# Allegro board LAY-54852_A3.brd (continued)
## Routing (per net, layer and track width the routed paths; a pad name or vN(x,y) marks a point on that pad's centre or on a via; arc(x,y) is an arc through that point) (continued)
POR_B: length 193.2
  TOP w0.091: R1743.2 v1(21.25,61.23) ; v1(48.82,73.05) 51.12,73.05 51.5,73.43 57.77,73.43 61.17,70.03 70.32,70.03 70.42,69.93 91.77,69.93 94.34,67.36 95.41,67.36 97.79,64.98 97.79,64.55 98.31,64.04 R404.1 98.85,64.04 98.94,64.13 98.94,64.96 99.12,65.13 100.02,65.13 100.32,64.82 U802.2 ; v1(33.38,72.69) 33.74,73.05 v1(42.33,73.05) ; v1(32.35,64.88) 32.35,64.88 31.95,65.28 26.19,65.28 25.04,66.43 24.07,66.43 21.5,68.99 v1(21.5,69.19) ; Q1408.1 v1(21.38,65.39) ; D1408.A 23.22,45.01 v1(21.72,45.01) 20.57,46.16 19.79,46.16 19.22,46.73 19.22,48.14 19.31,48.24 24.11,48.24 24.21,48.14 24.21,46.91 24.51,46.6 32.37,46.6 33.33,47.56 42.86,47.56 43.97,48.66 46.9,48.66 49.3,51.06 v1(49.53,51.06)
  TOP w0.104: U701.9 60.89,29.95 60.36,29.43 55.39,29.43 54.75,28.8 v1(54.5,28.8)
  BOTTOM w0.091: v1(21.72,45.01) 22.85,46.13 22.85,59.38 21.25,60.98 v1(21.25,61.23) 21.62,61.61 21.62,65.15 v1(21.38,65.39) 21.38,69.07 v1(21.5,69.19) ; v1(32.35,64.88) 32.44,64.88 32.82,65.26 32.82,72.13 v1(33.38,72.69) ; v1(42.33,73.05) v1(48.82,73.05) ; v1(54.5,28.8) 50.98,32.31 50.98,46.11 49.53,47.56 v1(49.53,51.06)
RC_BT_MODE0: length 24.8
  TOP w0.091: U1404.15 29.5,64.31 29.87,64.68 31.58,64.68 40.82,55.44 40.82,52.24 39.64,51.05 SW601.7 37.25,51.05 R608.1 R609.1
RC_BT_MODE1: length 22.8
  TOP w0.091: U1404.14 29.9,64.37 29.99,64.46 31.49,64.46 40.51,55.44 40.51,53.01 39.83,52.32 SW601.5 37.8,52.32 37.25,52.88 R607.1 R610.1
RC_BT_MODE2: length 20.3
  TOP w0.091: U1404.13 31.8,63.84 37.29,58.35 37.29,57.23 38.82,55.7 39.79,55.7 40.2,55.28 40.2,53.89 39.91,53.59 SW601.3 37.21,53.59 R606.1 R611.1
RC_BT_MODE3: length 13.1
  TOP w0.091: U1404.12 32.1,63.23 36.75,58.58 R605.1 R612.1 38.08,54.86 SW601.1
RC_NSEL: length 65.3
  TOP w0.091: R1815.2 8.79,69.97 8.38,70.39 7.82,70.39 6.95,69.52 5.41,69.52 5.12,69.23 5.12,67.48 5.03,67.39 3.42,67.39 D1413.C ; R1815.2 8.79,68.75 Q1405.3 ; R1815.2 10.54,69.88 11.61,70.95 16.21,70.95 16.61,70.55 16.61,69.24 17.13,68.72 21.47,68.72 23.98,66.21 24.73,66.21 v1(25.56,65.38) 25.87,65.06 28.34,65.06 29.1,64.3 U1404.16 29.07,63.81 U1404.1 ; v1(20.54,39.32) 20.84,39.02 U1408.12
  BOTTOM w0.091: v1(25.56,65.38) 24.93,64.75 24.93,61.21 23.28,59.57 23.28,45.13 20.54,42.38 v1(20.54,39.32)
RC_SEL: length 48.1
  TOP w0.091: D1412.C 3.17,65.15 4.81,65.15 5.67,66.01 6.37,66.01 6.55,66.19 R1754.1 ; v1(12.71,65.65) 9.15,65.65 8.16,66.63 Q1405.1 7.41,66.83 7.17,66.59 R1754.1 ; R1752.2 6.55,66.59 R1754.1 ; R1449.2 28.15,51.41 26.24,53.33 25.06,53.33 24.8,53.07 24.8,50.8 22.8,48.8 17.64,48.8 14.8,51.65 v1(14.42,51.65)
  BOTTOM w0.091: v1(12.71,65.65) 12.59,65.65 12.09,65.15 12.09,60.55 13.98,58.66 13.98,52.09 v1(14.42,51.65)
REG_FT_1V8: length 5.9
  TOP w0.254: U1706.49 3.72,31.37 C1422.1
  TOP w0.508: L1404.2 2.07,34.74 3.45,33.36 C1421.1 3.55,32.8 C1422.1
RTC_CLKO: length 124.2
  TOP w0.091: v1(48.43,48.34) 47.12,47.03 v1(44.25,47.03) ; R959.2 119.84,25.16 119.93,25.26 121.08,25.26 122.53,23.8 v1(122.53,16.41)
  BOTTOM w0.091: U1004.6 44.15,50.04 44.5,49.69 44.5,48.57 44.83,48.24 TP1021.1 v1(44.25,47.03) ; v1(48.43,48.34) 50.51,46.26 50.51,37.29 49.71,36.49 49.71,30.73 53.66,26.78 53.66,19.33 55.2,17.78 66.53,17.78 66.99,17.32 78.4,17.32 79.21,16.52 96.72,16.52 98.97,18.77 113.12,18.77 114.2,17.7 114.96,17.7 116.21,16.44 122.5,16.44 v1(122.53,16.41)
RTC_NINTA: length 120.2
  TOP w0.091: R807.2 107.11,56.43 106.88,56.2 v1(106.65,56.2)
  BOTTOM w0.091: v1(106.65,56.2) 106.65,56.97 107.56,57.88 107.56,66.29 106.29,67.57 106.29,71.43 105.4,72.32 104.16,72.32 101.76,74.72 90.64,74.72 87.22,71.3 84.98,71.3 84.55,71.72 82.21,71.72 82.21,71.73 81.42,71.73 81.06,71.36 73.73,71.36 68.44,76.66 54.91,76.66 48.65,70.4 48.65,66.61 48.07,66.02 43.51,66.02 32.53,55.04 32.53,52.64 33.02,52.15 34.44,52.15 35.84,50.75 TP1019.1
  BOTTOM w0.203: R1075.2 37.43,49.71 R1084.1 38.21,50.66 TP1019.1 38.59,51.04 U1004.13
SAI1_RXD0: length 82.6
  TOP w0.081: 91.24,57 91.24,56.45 U101.B14
  TOP w0.091: 91.24,57 91.24,58.39 93.28,60.43 95.11,60.43 96.85,58.69 98.5,58.69 102.78,54.41 114.31,54.41 116.64,56.74 116.64,58.59 119.03,60.97 123.64,60.97 123.8,60.82 126.42,60.82 127.14,61.54 128.2,61.54 v1(128.37,61.37) ; R909.1 126.36,28.84 125.79,29.41 125.79,32.29 125.23,32.84 v1(125.23,33.5)
  BOTTOM w0.091: v1(128.37,61.37) 128.22,61.23 128.22,38.42 125.23,35.44 v1(125.23,33.5)
SAI1_TXC: length 82.4
  TOP w0.081: U101.B15 91.49,56.35 91.75,56.61 91.75,56.86
  TOP w0.091: R1784.1 129.64,28.18 128.84,28.99 128.23,28.99 127.09,30.12 127.09,33.24 126.1,34.23 124.42,34.23 v1(124.33,34.14) ; 91.75,56.86 91.75,58.28 92.22,58.75 93.05,58.75 93.85,57.95 98.62,57.95 102.59,53.97 114.49,53.97 117.08,56.56 117.08,58.29 119.17,60.38 126.6,60.38 126.96,60.74 127.46,60.74 v1(127.62,60.58)
  BOTTOM w0.091: v1(124.33,34.14) 124.33,35.14 127.78,38.59 127.78,60.35 127.62,60.51 v1(127.62,60.58)
SAI1_TXD0: length 222.2
  TOP w0.091: v1(125.75,33.3) 126.28,32.77 126.28,29.84 127.44,28.68 R1786.1 ; U101.A15 91.49,58.33 93.37,60.21 95.02,60.21 96.92,58.31 98.57,58.31 102.68,54.19 114.4,54.19 116.86,56.65 116.86,58.5 119.12,60.75 123.55,60.75 123.71,60.6 126.51,60.6 127.14,61.24 127.74,61.24 127.98,61 128.62,61 v1(128.93,61.31)
  TOP w0.381: R605.2 35.91,57.18 TP604.1 34.65,57.71 34.18,58.18 v1(34.18,58.77)
  BOTTOM w0.091: v1(125.75,33.3) 125.75,35.64 128.44,38.33 128.44,60.82 v1(128.93,61.31) 129.43,61.81 129.43,79.63 125.53,83.54 40.32,83.54 36.62,79.84 36.62,61.28 34.18,58.84 v1(34.18,58.77)
SAI1_TXFS: length 228.3
  TOP w0.091: v1(128.3,61.9) 128.11,61.9 127.09,62.92 125.01,62.92 123.49,61.4 119.14,61.4 116.42,58.68 116.42,56.83 114.22,54.63 102.87,54.63 98.59,58.91 96.94,58.91 95.2,60.65 93.19,60.65 90.99,58.45 U101.A14 ; v1(33.71,57.95) 33.71,56.99 34.65,56.05 TP603.1 34.87,54.06 R606.2 ; R1785.1 128.54,28.36 126.65,30.25 126.65,33.17 125.88,33.95 125.13,33.95 v1(124.7,33.52)
  BOTTOM w0.091: v1(33.71,57.95) 33.95,57.95 36.84,60.84 36.84,79.75 40.41,83.32 125.44,83.32 129.2,79.55 129.2,62.8 v1(128.3,61.9) 127.99,61.59 127.99,38.5 124.7,35.21 v1(124.7,33.52)
SAI3_MCLK: length 56.1
  TOP w0.091: U804.3 100.69,72.95 101.25,73.5 v1(101.4,73.5) ; v1(102.35,33.9) 102.35,32.23 R1209.1
  BOTTOM w0.091: v1(102.35,33.9) 102.88,34.44 109.6,34.44 112.02,36.86 112.02,46.68 100.99,57.71 100.99,72.27 101.4,72.68 v1(101.4,73.5)
SAI3_RXC: length 63.3
  TOP w0.091: v1(109.51,29.27) 109.23,29.55 108.16,29.55 R1206.1 ; U803.3 v1(132.71,71.5)
  BOTTOM w0.091: v1(109.51,29.27) 109.51,30.17 111.2,31.85 126.05,31.85 126.65,32.45 126.65,35.61 129.1,38.06 129.1,56.17 132.68,59.75 132.68,69.17 132.03,69.82 132.03,70.82 v1(132.71,71.5)
SAI3_RXD: length 62.1
  TOP w0.091: U803.12 v1(129.81,70.7) ; R1208.1 v1(108.76,29.18)
  BOTTOM w0.091: v1(129.81,70.7) 131.81,68.7 131.81,61.72 128.66,58.57 128.66,38.24 126.21,35.79 126.21,32.63 125.87,32.29 111.02,32.29 108.76,30.03 v1(108.76,29.18)
SAI3_RXFS: length 63.3
  TOP w0.091: v1(109.46,28.53) 109.35,28.42 109.35,27.79 R1205.1 ; U803.16 v1(132.57,70.09)
  BOTTOM w0.091: v1(132.57,70.09) 132.91,69.75 132.91,59.61 129.32,56.02 129.32,37.97 126.86,35.52 126.86,32.35 126.14,31.63 111.29,31.63 109.89,30.23 109.89,29.06 109.46,28.63 v1(109.46,28.53)
SAI3_TXD: length 65.2
  TOP w0.091: v1(108.76,28.54) 108.76,28.19 R1207.1 ; U803.9 130.21,71.9 v1(129.81,72.3)
  BOTTOM w0.091: v1(108.76,28.54) 109.14,28.92 109.14,30.1 111.11,32.07 125.96,32.07 126.43,32.54 126.43,35.7 128.88,38.15 128.88,56.46 131.74,59.32 131.74,60.26 132.25,60.77 132.25,68.88 130.76,70.36 130.76,71.24 129.81,72.19 v1(129.81,72.3)
SD1_CLK: length 23.8
  TOP w0.081: U501.M6 105.23,38.65 105.23,37.45
  TOP w0.091: U101.U11 89.49,46.51 97.81,38.19 98.88,38.19 TP503.1 101.15,38.14 102.43,36.87 104.82,36.87 105.23,37.28 105.23,37.45
SD1_CMD: length 23.9
  TOP w0.081: 101.87,39.15 104.23,39.15 U501.M5 ; 89.74,48.76 89.74,48.24
  TOP w0.091: 89.74,48.76 89.74,48.96 U101.T11 ; 89.74,48.24 89.74,46.57 95.58,40.74 TP502.1 97.22,40.23 97.31,40.14 98.14,40.14 98.26,40.02 R502.2 98.26,39.36 99.08,38.55 99.23,38.55 99.37,38.69 99.37,39.14 99.43,39.2 99.67,39.2 99.73,39.14 99.73,38.7 99.88,38.55 99.88,38.55 100.13,38.55 100.32,38.74 100.32,39.02 100.41,39.11 100.72,39.11 100.82,39.02 100.82,38.72 100.99,38.55 101.56,38.55 101.65,38.64 101.65,38.93 101.87,39.15
SD1_DATA0: length 23.9
  TOP w0.076: U101.T13 90.74,48.95
  TOP w0.081: 90.74,47.26 91.26,46.74 ; 90.74,48.95 90.74,48.21 ; 102.33,44.65 103.24,44.65
  TOP w0.091: 103.24,44.65 U501.A3 ; 102.33,44.65 101.85,44.16 101.38,44.16 101.1,43.89 101.1,43.28 101.01,43.19 100.72,43.19 100.59,43.32 100.08,43.32 99.99,43.23 99.99,43 100.1,42.89 100.23,42.89 100.32,42.8 100.32,42.67 100.23,42.58 99.73,42.58 99.61,42.69 99.61,43.23 99.44,43.41 98,43.41 97.81,43.22 R501.2 97.4,42.84 97.16,43.07 97.16,43.85 97.09,43.92 96.84,43.92 96.75,43.83 TP501.1 96.37,42.87 96.28,42.96 96.28,43.85 96.18,43.94 96,43.94 95.91,43.85 95.91,42.96 95.82,42.87 94.94,42.87 91.26,46.55 91.26,46.74 ; 90.74,48.21 90.74,47.26
SD1_DATA1: length 23.7
  TOP w0.081: 91.25,47.79 91.58,47.46 91.58,47.35 91.47,47.25 91.47,47.13 91.59,47.02 91.7,47.02 91.76,47.07 91.88,47.07 ; U101.T14 91.25,48.95 91.25,48.2
  TOP w0.091: U501.A4 104.06,44.48 104.06,45.14 103.97,45.23 101.06,45.23 100.97,45.14 100.97,44.48 100.88,44.39 97.42,44.39 97.3,44.51 97.3,44.99 97.19,45.09 97.06,45.09 96.96,44.99 96.96,44.51 96.87,44.41 96.69,44.41 96.6,44.51 96.6,45.09 96.51,45.18 96.33,45.18 96.24,45.09 96.24,44.51 96.14,44.41 95.96,44.41 95.87,44.51 95.87,45.09 95.78,45.18 95.6,45.18 95.5,45.09 95.5,44.51 95.41,44.41 95.23,44.41 95.14,44.51 95.14,44.9 95.05,44.99 94.86,44.99 94.77,44.9 94.77,44.51 94.68,44.41 94.25,44.41 94.17,44.5 94.17,44.67 94.2,44.71 94.36,44.71 94.41,44.76 94.41,44.91 94.32,45 93.65,45 93.47,45.17 93.47,45.41 93.32,45.56 93.08,45.56 92.96,45.69 92.96,45.82 93.01,45.87 93.01,46.05 92.92,46.15 92.77,46.15 92.7,46.08 92.57,46.08 92.44,46.21 92.44,46.34 92.45,46.35 92.45,46.5 91.88,47.07 ; 91.25,48.2 91.25,47.79
SD1_DATA2: length 23.8
  TOP w0.081: 91.74,47.99 92.11,47.62 92.79,47.62 92.87,47.54 92.87,47.17 92.95,47.08 93.11,47.08 93.19,47.17 93.19,47.54 93.27,47.62 93.44,47.62 93.52,47.54 93.52,47.17 93.6,47.08 93.76,47.08 93.84,47.17 93.84,47.54 93.92,47.62 94.78,47.62 ; U101.T15 91.49,49.06 91.74,48.81 91.74,48.4
  TOP w0.091: 91.74,47.99 91.74,48.4 ; U501.A5 104.75,44.67 104.75,45.05 104.92,45.22 105.16,45.22 105.34,45.4 105.34,45.53 105.06,45.81 104.49,45.81 104.38,45.7 100.19,45.7 100.1,45.79 100.1,46.13 100.01,46.22 99.82,46.22 99.73,46.13 99.73,45.79 99.64,45.7 99.46,45.7 99.37,45.79 99.37,46.13 99.27,46.22 99.09,46.22 99,46.13 99,45.79 98.91,45.7 98.73,45.7 98.63,45.79 98.63,46.13 98.54,46.22 98.36,46.22 98.27,46.13 98.27,45.79 98.18,45.7 97.99,45.7 97.9,45.79 97.9,46.13 97.81,46.22 97.63,46.22 97.54,46.13 97.54,45.79 97.45,45.7 97.26,45.7 97.17,45.79 97.17,46.13 97.08,46.22 96.9,46.22 96.81,46.13 96.81,45.79 96.71,45.7 96.53,45.7 96.44,45.79 96.44,46.18 95,47.62 94.78,47.62
SD1_DATA3: length 23.8
  TOP w0.076: 102.28,44.05 102.39,44.15 102.73,44.15 U501.B2
  TOP w0.091: U101.U13 90.49,46.9 95.17,42.22 96.18,42.22 96.27,42.13 96.27,41.88 96.36,41.79 96.54,41.79 96.64,41.88 96.64,42.13 96.73,42.22 96.91,42.22 97,42.13 97,41.88 97.09,41.79 97.28,41.79 97.37,41.88 97.37,42.13 97.46,42.22 97.64,42.22 97.73,42.13 97.73,41.88 97.82,41.79 98.01,41.79 98.1,41.88 98.1,42.13 98.19,42.22 98.37,42.22 98.46,42.13 98.46,41.88 98.56,41.79 98.74,41.79 98.83,41.88 98.83,42.13 98.92,42.22 99.1,42.22 99.2,42.13 99.2,41.88 99.29,41.79 99.47,41.79 99.56,41.88 99.56,42.13 99.65,42.22 99.84,42.22 99.93,42.13 99.93,41.88 100.02,41.79 100.2,41.79 100.29,41.88 100.29,42.13 100.39,42.22 100.57,42.22 100.66,42.13 100.66,41.88 100.75,41.79 100.93,41.79 101.15,42.01 101.45,42.01 101.57,41.89 101.57,41.85 101.63,41.79 101.82,41.79 101.89,41.86 101.89,42.22 101.81,42.31 101.49,42.31 101.41,42.38 101.41,43.85 101.51,43.95 102.18,43.95 102.28,44.05
SD1_DATA4: length 23.8
  TOP w0.076: 102.34,43.65 103.23,43.65 U501.B3
  TOP w0.081: 90.24,48.22 90.24,48.95 U101.T12
  TOP w0.091: 102.34,43.65 101.82,43.65 101.72,43.55 101.72,42.66 101.78,42.61 102.01,42.61 102.15,42.46 102.15,41.21 102.07,41.12 101.84,41.12 101.75,41.22 101.75,41.48 101.66,41.57 101.13,41.57 101.03,41.48 101.03,41.27 100.94,41.18 100.76,41.18 100.67,41.27 100.67,41.48 100.58,41.57 100.39,41.57 100.3,41.48 100.3,41.27 100.21,41.18 100.03,41.18 99.94,41.27 99.94,41.48 99.85,41.57 99.66,41.57 99.57,41.48 99.57,41.27 99.48,41.18 99.3,41.18 99.21,41.27 99.21,41.48 99.11,41.57 98.93,41.57 98.84,41.48 98.84,41.27 98.75,41.18 98.57,41.18 98.47,41.27 98.47,41.4 98.38,41.49 95.52,41.49 90.24,46.76 90.24,48.22
SD1_DATA5: length 23.7
  TOP w0.076: U501.B4 103.73,44.15 103.73,44.87
  TOP w0.081: 90.99,47.67 91.14,47.52
  TOP w0.091: 91.14,47.52 91.14,47.19 94.18,44.16 94.98,44.16 95.07,44.06 95.07,43.31 95.2,43.18 95.45,43.18 95.54,43.28 95.54,43.99 95.71,44.16 97.22,44.16 97.42,43.95 97.42,43.55 97.5,43.46 97.7,43.46 97.77,43.54 97.77,44.06 97.86,44.16 98.05,44.16 98.14,44.06 98.14,43.72 98.24,43.63 98.42,43.63 98.51,43.72 98.51,44.06 98.6,44.16 98.8,44.16 98.89,44.06 98.89,43.78 98.98,43.68 99.17,43.68 99.26,43.78 99.26,44.06 99.35,44.16 99.53,44.16 99.62,44.06 99.62,43.78 99.71,43.68 99.9,43.68 99.99,43.78 99.99,44.06 100.08,44.16 100.26,44.16 100.35,44.06 100.35,43.78 100.45,43.68 100.63,43.68 100.72,43.78 100.72,44.06 100.81,44.16 101,44.16 101.27,44.42 101.27,44.87 101.36,44.97 101.58,44.97 101.7,44.85 101.7,44.57 101.79,44.48 101.92,44.48 102.01,44.57 102.01,44.85 102.13,44.97 103.64,44.97 103.73,44.87 ; U101.U14 90.99,47.67
SD1_DATA6: length 24
  TOP w0.076: U501.B5 104.33,43.9 104.23,44 104.23,44.66
  TOP w0.081: 92.44,47.05 92.35,47.14 92.28,47.14 91.49,47.93
  TOP w0.091: 104.23,44.66 104.54,44.96 104.54,45.39 104.45,45.48 100.26,45.48 100.17,45.39 100.17,45.14 100.3,45.01 100.61,45.01 100.68,44.93 100.68,44.7 100.59,44.61 99.9,44.61 99.81,44.7 99.81,45.39 99.72,45.48 99.53,45.48 99.44,45.39 99.44,44.7 99.35,44.61 99.17,44.61 99.07,44.7 99.07,45.39 98.98,45.48 98.8,45.48 98.71,45.39 98.71,44.7 98.62,44.61 98.43,44.61 98.34,44.7 98.34,45.39 98.25,45.48 98.07,45.48 97.98,45.39 97.98,44.7 97.89,44.61 97.7,44.61 97.61,44.7 97.61,45.37 97.52,45.47 95.35,45.47 95.11,45.22 94.09,45.22 93.32,46 93.32,46.17 92.44,47.05 ; 91.49,47.93 U101.U15
SD1_DATA7: length 23.9
  TOP w0.076: U501.B6 105.23,44.15 105.63,44.15 105.74,44.25 105.74,44.49
  TOP w0.081: 94.6,47.87 94.55,47.92 92.21,47.92 91.99,48.13
  TOP w0.091: 105.74,44.49 105.74,44.84 106.02,45.12 106.37,45.12 106.56,45.32 106.56,46.35 106.47,46.44 105.37,46.44 105.27,46.35 105.27,46.24 105.18,46.15 105,46.15 104.91,46.24 104.91,46.28 104.75,46.43 104.13,46.43 104.04,46.34 104.04,46.01 103.95,45.92 103.53,45.92 103.44,46.01 103.44,46.35 103.34,46.44 103.16,46.44 103.07,46.35 103.07,46.01 102.98,45.92 102.8,45.92 102.7,46.01 102.7,46.35 102.61,46.44 102.42,46.44 102.33,46.35 102.33,46.01 102.24,45.92 102.05,45.92 101.96,46.01 101.96,46.35 101.87,46.44 101.69,46.44 101.6,46.35 101.6,46.01 101.51,45.92 101.32,45.92 101.23,46.01 101.23,46.35 101.14,46.44 100.96,46.44 100.87,46.35 100.87,46.01 100.77,45.92 100.59,45.92 100.5,46.01 100.5,46.35 100.41,46.44 96.51,46.44 95.09,47.87 94.6,47.87 ; 91.99,48.13 U101.U16
SD1_STROBE: length 23.7
  TOP w0.081: 101.87,40.65 104.24,40.65 U501.H5
  TOP w0.091: 101.87,40.65 101.41,40.65 101.32,40.56 101.32,40.11 101.22,40.02 101.04,40.02 100.95,40.11 100.95,40.56 100.86,40.65 100.68,40.65 100.58,40.56 100.58,40.11 100.49,40.02 100.31,40.02 100.22,40.11 100.22,40.56 100.13,40.65 99.85,40.65 99.75,40.56 99.75,40.03 99.6,39.88 99.47,39.88 99.28,40.07 99.28,40.54 TP505.1 98.81,40.75 98.72,40.66 98.72,40.23 98.63,40.14 98.44,40.14 98.35,40.23 98.35,40.97 98.06,41.26 95.37,41.26 89.99,46.63 U101.U12
SD2_CLK: length 35.4
  TOP w0.081: 92.69,50.95 92.25,50.95 U101.M16
  TOP w0.091: 92.69,50.95 95.54,50.95 96.63,49.87 118.53,49.87 118.63,49.97 118.63,50.08 118.53,50.17 118.11,50.17 118.02,50.26 118.02,50.4 118.11,50.5 118.54,50.5 118.63,50.59 118.63,51.69 118.77,51.83 119.54,51.83 119.63,51.92 119.63,52.05 119.53,52.14 118.72,52.14 118.63,52.23 118.63,52.9 118.72,52.99 119.43,52.99 119.8,52.63 120.6,52.63 R1061.1
SD2_CMD: length 35.4
  TOP w0.091: U101.M17 95.6,51.21 96.72,50.08 117.35,50.08 118.41,51.14 118.41,53.57 118.58,53.74 118.99,53.74 119.08,53.83 119.08,54.03 118.99,54.13 118.61,54.13 118.41,54.33 118.41,54.88 119.09,55.56 R311.2 120.84,55.58 R1060.1
SD2_DATA0: length 36.4
  TOP w0.091: U101.N17 95.48,50.71 96.53,49.65 98.42,49.65 98.51,49.56 98.51,49.15 98.6,49.06 98.78,49.06 98.87,49.15 98.87,49.56 98.96,49.65 99.15,49.65 99.24,49.56 99.24,49.15 99.33,49.06 99.51,49.06 99.6,49.15 99.6,49.56 99.7,49.65 99.88,49.65 99.97,49.56 99.97,49.15 100.06,49.06 100.24,49.06 100.34,49.15 100.34,49.56 100.43,49.65 117,49.65 117.21,49.44 117.21,48.91 117.35,48.77 117.57,48.77 117.67,48.86 117.67,49.51 117.8,49.65 117.99,49.65 118.09,49.56 118.09,49.04 118.18,48.95 118.43,48.95 118.49,49.01 118.49,49.52 118.62,49.65 118.91,49.65 119.1,49.83 119.1,50.63 119.51,51.04 119.96,51.04 120.17,50.83 R1062.1 120.84,50.84 R310.2
SD2_DATA1: length 35.5
  TOP w0.081: 92.78,50.46 92.24,50.46 U101.N16
  TOP w0.091: R1063.1 120.37,50.24 119.69,50.24 119.43,49.99 119.43,48.69 119.06,48.31 118.6,48.31 118.51,48.4 118.51,48.52 118.42,48.62 118.24,48.62 118.14,48.52 118.14,48.4 118.05,48.31 117.44,48.31 116.99,48.76 116.99,49.26 116.82,49.43 107.12,49.43 106.53,48.84 105.33,48.84 105.24,48.94 105.24,48.98 105.15,49.07 104.96,49.07 104.87,48.98 104.87,48.94 104.78,48.84 104.6,48.84 104.51,48.94 104.51,49.17 104.42,49.26 104.23,49.26 104.14,49.17 104.14,48.94 104.05,48.84 103.87,48.84 103.78,48.94 103.78,49.17 103.68,49.26 103.5,49.26 103.41,49.17 103.41,48.94 103.32,48.84 103.14,48.84 103.04,48.94 103.04,49.17 102.95,49.26 102.77,49.26 102.68,49.17 102.68,48.94 102.59,48.84 102.4,48.84 102.31,48.94 102.31,49.17 102.22,49.26 102.04,49.26 101.95,49.17 101.95,48.94 101.86,48.84 98.32,48.84 97.74,49.43 96.44,49.43 95.42,50.46 92.78,50.46
SD2_DATA2: length 35.5
  TOP w0.091: U101.L17 95.74,51.71 96.93,50.52 116.78,50.52 117.97,51.71 117.97,57.03 120.16,59.21 R1064.1
SD2_DATA3: length 35.3
  TOP w0.081: U101.L16 92.24,51.45 92.71,51.45
  TOP w0.091: R1065.1 120.17,57.85 118.19,55.87 118.19,51.27 117.23,50.3 96.81,50.3 95.66,51.45 92.71,51.45
SD2_NCD: length 64.4
  TOP w0.081: v1(90.47,50.21) U101.P12
  TOP w0.091: R1052.2 137.16,40.57 136.87,40.86 U1707.4 135.8,40.86 135.23,40.28 133.41,40.28 131.83,38.7 128.64,38.7 125.73,35.79 122.42,35.79 119.64,38.56 119.64,45.3 120.84,46.5 R1051.1 120.26,48.5 119.86,48.09 117.24,48.09 116.13,49.21 107.39,49.21 106.66,48.48 97.54,48.48 v1(97.02,49)
  BOTTOM w0.081: v1(90.47,50.21) 94.78,50.21
  BOTTOM w0.091: v1(97.02,49) 95.82,50.21 94.78,50.21
SD2_NDET: length 34
  TOP w0.091: U1707.2 131.72,41.81 TP1914.1 131.7,40.13 R1054.2 131.82,39.23 131.51,38.92 128.55,38.92 125.64,36.01 122.51,36.01 119.86,38.65 119.86,45.21 121.59,46.94 D1004.1 ; D1004.1 121.59,47.01 R1051.2 ; D1004.1 122.64,47.01 124.03,48.4 J1002.9
SD2_NRST: length 73.1
  TOP w0.081: U101.P10 89.37,50.21 89.45,50.12 89.45,49.7 v1(89.49,49.66)
  TOP w0.091: v1(54.56,26.32) 54.73,26.32 56.9,24.15 R723.2
  TOP w0.102: v1(74.77,18.27) 76.64,18.27 77.24,18.87 77.24,23.66 78.59,25.01 78.59,33.46 79.4,34.27 79.4,36.27 85.58,42.45 v1(85.58,44.23)
  BOTTOM w0.081: v1(89.49,49.66) 89.45,49.63 89.45,48.8 R312.2 89.45,48.77 89.45,46.74
  BOTTOM w0.091: v1(54.56,26.32) 54.51,26.27 54.51,19.38 55.68,18.21 66.47,18.21 66.71,18.45 74.58,18.45 v1(74.77,18.27) ; 89.45,46.74 89.45,45.76 87.92,44.23 v1(85.58,44.23)
SD2_VSEL: length 79
  TOP w0.081: U101.P14 91.75,49.45 91.75,49.09 91.88,48.95 92.13,48.95 92.24,48.84 92.24,48.45
  TOP w0.091: 92.24,48.45 92.61,48.08 95.19,48.08 96.52,46.76 107.29,46.76 111.32,42.73 111.32,37.56 v1(111.21,37.45)
  TOP w0.152: v1(71,26.58) 70.32,26.58 68.95,27.95 U701.29
  BOTTOM w0.091: v1(71,26.58) 73.1,26.58 75.37,24.32 76.66,24.32 76.95,24.6 91.86,24.6 102.35,35.09 109.16,35.09 111.21,37.14 v1(111.21,37.45)
SD3_CLK: length 99.5
  TOP w0.081: U101.T16 92.14,49.21 92.39,48.96 92.8,48.96
  TOP w0.091: J1707.9 131.35,5.56 131.87,5.04 131.97,5.04 132.11,4.9 132.84,4.9 133.24,4.5 133.24,2.73 TP912.1 133.26,1.89 132.92,1.55 113.21,1.55 113.12,1.64 113.12,1.95 113.03,2.05 112.85,2.05 112.76,1.95 112.76,1.64 112.66,1.55 112.48,1.55 112.39,1.64 112.39,1.95 112.3,2.05 112.12,2.05 112.02,1.95 112.02,1.64 111.93,1.55 111.75,1.55 111.66,1.64 111.66,1.95 111.57,2.05 111.38,2.05 111.29,1.95 111.29,1.64 111.2,1.55 110.23,1.55 108.48,3.3 108.48,12.55 113.08,17.15 113.08,22.52 114.48,23.92 114.48,39.97 107.44,47.02 96.57,47.02 94.63,48.96 92.8,48.96
SD3_CMD: length 99.6
  TOP w0.091: J1707.11 130.85,5.56 131.92,4.5 R952.2 132.8,4.5 132.92,4.38 132.92,3.51 TP913.1 131.18,1.77 121.44,1.77 121.35,1.86 121.35,1.98 121.26,2.08 121.08,2.08 120.99,1.98 120.99,1.86 120.9,1.77 120.71,1.77 120.62,1.86 120.62,1.98 120.53,2.08 120.35,2.08 120.26,1.98 120.26,1.86 120.16,1.77 119.98,1.77 119.89,1.86 119.89,1.98 119.8,2.08 119.62,2.08 119.52,1.98 119.52,1.86 119.43,1.77 119.25,1.77 119.16,1.86 119.16,1.98 119.07,2.08 118.88,2.08 118.79,1.98 118.79,1.86 118.7,1.77 118.52,1.77 118.43,1.86 118.43,1.98 118.34,2.08 118.15,2.08 118.06,1.98 118.06,1.86 117.97,1.77 117.79,1.77 117.7,1.86 117.7,1.98 117.6,2.08 117.42,2.08 117.33,1.98 117.33,1.86 117.24,1.77 117.06,1.77 116.96,1.86 116.96,1.98 116.87,2.08 116.69,2.08 116.6,1.98 116.6,1.86 116.51,1.77 116.32,1.77 116.23,1.86 116.23,1.98 116.14,2.08 115.96,2.08 115.87,1.98 115.87,1.86 115.78,1.77 115.59,1.77 115.5,1.86 115.5,1.98 115.41,2.08 115.23,2.08 115.14,1.98 115.14,1.86 115.04,1.77 114.86,1.77 114.77,1.86 114.77,2.17 114.68,2.26 114.39,2.26 114.3,2.18 114.3,1.92 114.18,1.8 113.95,1.8 113.81,1.93 113.81,2.12 113.67,2.26 110.1,2.26 108.7,3.66 108.7,12.46 113.3,17.05 113.3,22.43 114.7,23.83 114.7,40.18 107.58,47.3 96.67,47.3 94.76,49.21 U101.T17
SD3_DATA0: length 99.7
  TOP w0.081: 93.03,49.46 92.24,49.46 U101.R16
  TOP w0.091: 93.03,49.46 94.87,49.46 96.75,47.57 107.8,47.57 114.92,40.45 114.92,23.68 113.52,22.28 113.52,16.96 108.92,12.37 108.92,3.81 109.7,3.03 111.11,3.03 111.2,2.94 111.2,2.82 111.29,2.73 111.47,2.73 111.56,2.82 111.56,2.94 111.65,3.03 111.84,3.03 111.93,2.94 111.93,2.82 112.02,2.73 112.2,2.73 112.29,2.82 112.29,2.94 112.39,3.03 112.57,3.03 112.66,2.94 112.66,2.82 112.75,2.73 112.94,2.73 113.03,2.82 113.03,2.94 113.12,3.03 113.3,3.03 113.39,2.94 113.39,2.82 113.48,2.73 113.67,2.73 113.76,2.82 113.76,2.94 113.85,3.03 114.03,3.03 114.12,2.94 114.12,2.82 114.22,2.73 114.4,2.73 114.49,2.82 114.49,2.94 114.58,3.03 114.76,3.03 114.86,2.94 114.86,2.82 114.95,2.73 115.13,2.73 115.22,2.82 115.22,2.94 115.31,3.03 115.5,3.03 115.59,2.94 115.59,2.82 115.68,2.73 115.86,2.73 115.95,2.82 115.95,2.94 116.04,3.03 116.23,3.03 116.32,2.94 116.32,2.82 116.41,2.73 116.59,2.73 116.68,2.82 116.68,2.94 116.78,3.03 116.96,3.03 117.05,2.94 117.05,2.82 117.14,2.73 117.32,2.73 117.42,2.82 117.42,2.94 117.51,3.03 117.69,3.03 117.78,2.94 117.78,2.82 117.87,2.73 118.06,2.73 118.15,2.82 118.15,2.94 118.24,3.03 118.42,3.03 118.51,2.94 118.51,2.82 118.6,2.73 118.79,2.73 118.88,2.82 118.88,2.94 118.97,3.03 119.15,3.03 119.24,2.94 119.24,2.82 119.34,2.73 119.52,2.73 119.61,2.82 119.61,2.94 119.7,3.03 119.88,3.03 119.98,2.94 119.98,2.82 120.07,2.73 120.25,2.73 120.34,2.82 120.34,2.94 120.43,3.03 120.62,3.03 120.71,2.94 120.71,2.87 120.8,2.78 120.98,2.78 121.07,2.87 121.07,2.94 121.16,3.03 122.19,3.03 123.23,1.99 130.22,1.99 TP914.1 130.9,2.87 130.07,3.69 130.07,4.4 130.16,4.5 R951.2 130.93,4.99 130.35,5.56 J1707.13
SD3_DATA1: length 99.5
  TOP w0.091: U101.R17 95,49.71 96.88,47.83 108.04,47.83 108.66,47.2 108.79,47.2 109.29,47.7 109.42,47.7 109.55,47.57 109.55,47.44 109.05,46.94 109.05,46.81 109.18,46.69 109.31,46.69 109.8,47.18 109.93,47.18 110.06,47.05 110.06,46.92 109.57,46.43 109.57,46.3 109.7,46.17 109.83,46.17 110.32,46.66 110.45,46.66 110.58,46.53 110.58,46.4 110.09,45.91 110.09,45.78 110.21,45.65 110.34,45.65 110.84,46.15 110.97,46.15 111.1,46.02 111.1,45.89 110.6,45.39 110.6,45.26 115.14,40.73 115.14,23.58 113.74,22.18 113.74,16.87 109.14,12.28 109.14,4.06 109.85,3.36 110.85,3.36 110.94,3.45 110.94,3.52 111.03,3.61 111.22,3.61 111.31,3.52 111.31,3.45 111.4,3.36 111.58,3.36 111.67,3.45 111.67,3.52 111.77,3.61 111.95,3.61 112.04,3.52 112.04,3.45 112.13,3.36 112.31,3.36 112.41,3.45 112.41,3.52 112.5,3.61 112.68,3.61 112.77,3.52 112.77,3.45 112.86,3.36 113.05,3.36 113.14,3.45 113.14,3.52 113.23,3.61 113.41,3.61 113.5,3.52 113.5,3.45 113.59,3.36 113.78,3.36 113.87,3.45 113.87,3.52 113.96,3.61 114.14,3.61 114.23,3.52 114.23,3.45 114.33,3.36 114.51,3.36 114.6,3.45 114.6,3.52 114.69,3.61 114.87,3.61 114.97,3.52 114.97,3.45 115.06,3.36 115.24,3.36 115.33,3.45 115.33,3.52 115.42,3.61 115.61,3.61 115.7,3.52 115.7,3.45 115.79,3.36 115.97,3.36 116.06,3.45 116.06,3.52 116.15,3.61 116.34,3.61 116.43,3.52 116.43,3.45 116.52,3.36 122.42,3.36 123.57,2.21 128.97,2.21 TP1936.1 129.85,3.09 J1707.15
SD3_DATA2: length 99.5
  TOP w0.081: U101.P16 92.24,49.96 93,49.96
  TOP w0.091: 93,49.96 95.1,49.96 97.01,48.05 109.56,48.05 111.67,45.94 111.67,45.81 111.14,45.28 111.14,45.16 111.27,45.03 111.4,45.03 111.93,45.55 112.06,45.55 112.19,45.42 112.19,45.29 111.66,44.77 111.66,44.64 111.79,44.51 111.92,44.51 112.45,45.04 112.57,45.04 112.7,44.91 112.7,44.78 112.18,44.25 112.18,44.12 112.31,43.99 112.44,43.99 112.96,44.52 113.09,44.52 113.22,44.39 113.22,44.26 112.7,43.73 112.7,43.6 112.87,43.43 113.08,43.43 113.46,43.81 113.59,43.81 113.72,43.68 113.72,43.55 113.3,43.13 113.3,43 115.35,40.94 115.35,23.49 113.95,22.09 113.95,16.78 109.36,12.18 109.36,4.26 109.61,4 113.94,4 114.03,4.09 114.03,4.2 114.12,4.29 114.31,4.29 114.4,4.2 114.4,4.09 114.49,4 114.67,4 114.76,4.09 114.76,4.2 114.85,4.29 115.04,4.29 115.13,4.2 115.13,4.09 115.22,4 115.4,4 115.5,4.09 115.5,4.2 115.59,4.29 115.77,4.29 115.86,4.2 115.86,4.09 115.95,4 116.14,4 116.23,4.09 116.23,4.2 116.32,4.29 116.5,4.29 116.59,4.2 116.59,4.09 117.02,3.66 122.66,3.66 123.9,2.43 127.53,2.43 128.04,2.93 TP1937.1 129.35,3.74 J1707.17
SD3_DATA3: length 99.4
  TOP w0.091: J1707.19 128.85,3.81 128.38,3.34 127.71,3.34 TP917.1 127.07,2.71 124.18,2.71 122.99,3.9 117.2,3.9 116.52,4.58 113.13,4.58 113.04,4.48 113.04,4.38 112.95,4.29 112.77,4.29 112.68,4.38 112.68,4.53 112.58,4.63 112.4,4.63 112.31,4.53 112.31,4.38 112.22,4.29 112.04,4.29 111.94,4.38 111.94,4.53 111.85,4.63 111.67,4.63 111.58,4.53 111.58,4.38 111.49,4.29 111.3,4.29 111.21,4.38 111.21,4.53 111.12,4.63 110.94,4.63 110.85,4.53 110.85,4.38 110.76,4.29 110.57,4.29 110.48,4.38 110.48,4.53 110.39,4.63 109.84,4.63 109.58,4.89 109.58,12.09 114.17,16.69 114.17,22 115.57,23.4 115.57,41.58 115.48,41.67 115.16,41.67 115.07,41.76 115.07,41.95 115.16,42.04 115.48,42.04 115.57,42.13 115.57,42.46 115.27,42.77 115.14,42.77 114.55,42.19 114.42,42.19 114.29,42.31 114.29,42.44 114.88,43.03 114.88,43.16 114.75,43.29 114.62,43.29 114.03,42.7 113.91,42.7 113.78,42.83 113.78,42.96 114.36,43.55 114.36,43.68 113.81,44.23 113.81,44.36 113.95,44.51 113.95,44.63 113.82,44.76 113.69,44.76 113.55,44.62 113.42,44.62 113.29,44.75 113.29,44.88 113.44,45.02 113.44,45.15 113.31,45.28 113.18,45.28 113.03,45.14 112.9,45.14 112.77,45.27 112.77,45.39 112.92,45.54 112.92,45.67 112.79,45.8 112.66,45.8 112.51,45.65 112.38,45.65 112.25,45.78 112.25,45.91 112.4,46.06 112.4,46.19 112.27,46.32 112.14,46.32 112,46.17 111.87,46.17 111.74,46.3 111.74,46.43 111.88,46.58 111.88,46.71 111.75,46.83 111.62,46.83 111.48,46.69 111.35,46.69 111.22,46.82 111.22,46.95 111.36,47.09 111.36,47.22 111.24,47.35 111.11,47.35 110.96,47.21 110.83,47.21 109.77,48.27 97.23,48.27 95.29,50.21 U101.P17
SD3_NRST: length 70.4
  TOP w0.091: R821.2 v1(115.76,62.2) 116.51,62.2 R827.1 ; v1(119.41,36.46) 119.41,36.22 119.5,36.13 120.63,36.13 122.07,34.69 122.14,34.69 125.25,31.58 125.25,21.97 126.88,20.34 126.88,10.16 127.85,9.19 J1707.23 126.71,6.7 126.17,6.16 126.17,4.3 125.67,3.8 125.03,3.8 TP919.1
  BOTTOM w0.091: v1(115.76,62.2) 115.38,61.83 115.38,59.28 113.52,57.41 113.52,51.67 116.68,48.51 116.68,43.14 118.07,41.75 118.07,38.53 118.76,37.84 118.76,37.12 v1(119.41,36.46)
SD3_NWAKE: length 64.8
  TOP w0.091: v1(126.28,3.84) 126.4,3.97 R923.2 127.96,3.97 R1793.1 ; v1(125.75,5.1) 125.75,6.16 126.63,7.04 126.63,20.28 124.98,21.93 124.98,31.46 121.63,34.81 121.63,34.82 120.54,35.91 117.87,35.91 v1(117.77,35.8) ; R810.2 v1(111.18,56.04)
  BOTTOM w0.091: v1(126.28,3.84) 126.28,4.57 v1(125.75,5.1) ; v1(111.18,56.04) 111.33,55.88 111.33,50.55 114.07,47.81 114.07,42.13 115.79,40.42 115.79,35.99 116.49,35.29 117.26,35.29 v1(117.77,35.8)
SD_CLK: length 4.3
  TOP w0.091: R1061.2 122.71,52.86 D1006.1 122.74,53.26 122.89,53.42 123.76,53.42 124.39,52.8 J1002.5
SD_CMD: length 4.7
  TOP w0.091: J1002.3 124.7,55 123.51,56.19 122.75,56.19 122.48,56.45 D1005.1 121.84,56.9 R1060.2
SD_DATA0: length 4
  TOP w0.091: J1002.7 123.22,50.6 122.8,51.02 D1007.1 121.92,51.17 R1062.2
SD_DATA1: length 4.2
  TOP w0.091: J1002.8 123.15,49.5 122.8,49.85 D1008.1 122.37,50.2 121.93,49.77 R1063.2
SD_DATA2: length 4.5
  TOP w0.091: R1064.2 121.87,58.93 D1009.1 122.48,58.68 122.73,58.43 123.49,58.43 124.73,57.2 J1002.1
SD_DATA3: length 4.5
  TOP w0.091: J1002.2 124.67,56.1 123.37,57.4 122.68,57.4 122.48,57.59 D1010.1 121.65,57.91 R1065.2
SPI3_CLK: length 46.3
  TOP w0.091: v1(118.94,35.28) 119.47,34.75 120.06,34.75 122.26,32.55 122.26,30.43 v1(122.31,30.38) 122.26,30.33 122.26,30.25 122.15,30.14 U906.8
  TOP w0.102: U805.12 111.44,69.86 111.62,69.68 v1(111.62,69.57)
  BOTTOM w0.091: v1(118.94,35.28) 118.94,35.78 117.2,37.53 117.2,40.55 115.16,42.59 115.16,48.27 112.43,51 112.43,68.77 v1(111.62,69.57) ; v1(122.31,30.38) 122.16,30.23 U905.4
SPI3_CS0: length 48.5
  TOP w0.091: v1(119.83,33.98) 121.24,32.56 v1(121.24,30.43) 121.24,30.2 121.35,30.09 U906.10
  TOP w0.102: U805.16 v1(112.05,72.07)
  BOTTOM w0.091: U905.2 121.36,30.31 v1(121.24,30.43) ; v1(119.83,33.98) 120.48,34.62 120.48,35.41 120.39,35.5 119.84,35.5 117.64,37.71 117.64,40.85 115.69,42.8 115.69,48.36 112.86,51.19 112.86,71.26 v1(112.05,72.07)
SPI3_MISO: length 49.6
  TOP w0.091: U906.7 122.55,29.87 122.82,30.13 122.82,30.36 v1(122.84,30.39) 122.82,30.41 122.82,32.3 120.11,35.01 v1(120.11,35.13)
  TOP w0.102: U805.3 v1(110.64,72.42)
  BOTTOM w0.091: v1(110.64,72.42) 112.64,70.41 112.64,51.09 115.47,48.27 115.47,42.71 117.42,40.76 117.42,37.62 119.91,35.13 v1(120.11,35.13) ; U905.5 122.56,29.95 122.84,30.23 v1(122.84,30.39)
SPI3_MOSI: length 46.8
  TOP w0.091: v1(118.91,34.75) 119.1,34.75 119.31,34.54 119.91,34.54 121.75,32.7 121.75,30.44 v1(121.78,30.41) 121.75,30.39 U906.9
  TOP w0.102: U805.9 110.24,69.74 v1(110.03,69.53)
  BOTTOM w0.091: v1(118.91,34.75) 118.9,34.75 118.55,35.1 118.55,35.87 116.98,37.44 116.98,40.46 114.95,42.5 114.95,48.17 112.21,50.91 112.21,67.35 v1(110.03,69.53) ; U905.3 121.76,30.4 v1(121.78,30.41)
SPK_LN: length 5.9
  TOP w0.076: 104.27,26.1 104.27,26.57 U1709.B3
  TOP w0.102: 104.27,26.1 104.15,25.98 104.15,25.64 104.73,25.06 104.8,25.06 106.64,23.22 106.64,23.15 107.11,22.67 R1216.1
SPK_LP: length 2.2
  TOP w0.102: U1709.A1 105.7,26.32 106.41,25.62 R1214.1
SPK_RN: length 5.2
  TOP w0.076: 105.01,25.81 104.78,26.04 104.78,27.07 U1709.C3
  TOP w0.102: R1220.1 107.4,23.75 105.74,25.41 105.2,25.41 105.01,25.61 105.01,25.81
SPK_RP: length 3.5
  TOP w0.076: U1709.B2 105.27,26.58 105.27,26.21
  TOP w0.102: R1218.1 106.98,24.64 105.55,26.07 105.42,26.07 105.27,26.21
SPKOUTLN: length 9.9
  TOP w0.091: R1216.2 108.86,22.67 C1221.2 109,22.52 109,21.75 110.36,20.39 TP1943.1 111.2,20.77 112.01,21.58 112.01,23.04 113.66,24.7 C1218.2
SPKOUTLP: length 7.1
  TOP w0.091: C1218.1 113.27,25.95 112.53,25.95 111.98,25.4 TP1942.1 110.22,26.37 109.25,26.37 109,26.12 C1217.1 108.15,25.62 R1214.2
SPKOUTRN: length 7.9
  TOP w0.091: C1224.2 112.73,24.12 111.2,22.59 TP1945.1 110.39,22.86 110.39,23.8 110.26,23.93 109.29,23.93 109.01,23.65 C1227.2 108.86,23.65 R1220.2
SPKOUTRP: length 6
  TOP w0.091: C1224.1 112.64,25.43 112.01,24.79 112.01,24.54 TP1944.1 110.77,24.16 109.09,24.16 109,24.25 C1223.1 108.99,24.64 R1218.2
STAR_I2C_SCL: length 8.4
  TOP w0.091: R1443.2 64.52,73.49 J1406.4 J1406.3
STAR_I2C_SDA: length 8.4
  TOP w0.091: J1406.5 J1406.6 67.06,73.45 R1445.2
SUSCLK: length 5.2
  TOP w0.091: R919.1 119.68,17.93 121.1,16.51 J1707.50
SYS_EN: length 19.1
  TOP w0.254: R355.2 63.81,1.74 64.07,1.48 64.88,1.48 65.98,2.58 70.35,2.58 70.7,2.23 71.6,2.23 71.85,2.48 R352.2 72.79,3.68 72.79,7.63 73.45,8.28 73.45,10.25 74.33,11.13 D301.C
SYS_NRST: length 138.2
  TOP w0.091: R706.1 57.93,29.93 TP915.1 55.68,30.18 54.93,29.43 v1(54.46,29.43) ; v1(16.71,44.78) 16.72,44.79 D1409.A 20.29,45.03 19,46.32 19,48.25 19.21,48.45 24.28,48.45 24.42,48.31 24.42,47 24.61,46.82 31.9,46.82 33.08,48.01 36.43,48.01 v1(36.44,48.02) 36.45,48.01 43,48.01 43.88,48.88 46.81,48.88 49.17,51.24 49.17,51.27 v1(49.48,51.59) ; R1430.2 v1(12.63,60.54) ; R1427.2 38.12,81.9 38.12,82.65 C1410.1 38.17,83.25 37.92,83.5 23.35,83.5 22.68,82.84 20.18,82.84 19.76,82.41 v1(14.44,82.41)
  BOTTOM w0.091: v1(49.48,51.59) 49.53,51.59 49.95,51.17 49.95,47.45 51.37,46.02 51.37,32.52 v1(54.46,29.43) ; R1085.2 36.51,47.95 v1(36.44,48.02) ; v1(14.44,82.41) 13.95,81.93 13.95,62.63 12.63,61.31 v1(12.63,60.54) 15.73,57.44 15.73,51.93 16.71,50.95 v1(16.71,44.78)
TAMPER0: length 68.2
  TOP w0.081: v1(87.49,55.21) U101.D6
  TOP w0.091: v1(65.81,66.27) 65.81,66.31 66.16,66.66 89.85,66.66 90.96,65.55 90.96,62.5 89.9,61.44 89.9,60.78 89.65,60.53 89.65,59.93 v1(89.8,59.78) ; v1(65.04,70.9) 64.82,70.69 62.8,70.69 58.42,75.07 52.3,75.07 51.73,75.64 TP405.1 52.05,78.43 R1431.2 53.21,78.44 R1436.1 54.5,78.6 54.5,81.34 J1403.3
  BOTTOM w0.091: v1(89.8,59.78) 89.8,58.82 88.05,57.06 88.05,55.76 v1(87.49,55.21) ; v1(65.04,70.9) 65.04,67.08 65.81,66.31 v1(65.81,66.27)
TAMPER1: length 60.2
  TOP w0.081: v1(88.49,55.21) U101.D8
  TOP w0.091: J1403.4 55.39,80.23 R1437.1 55.4,78.43 R1432.2 57.76,78.43 TP406.1 58.1,75.7 62.81,70.99 64.19,70.99 v1(64.3,71.1) ; v1(90.02,60.37) 90.12,60.47 90.12,61.35 91.18,62.41 91.18,65.64 89.94,66.88 65.89,66.88 65.3,66.29 v1(65.3,66.02)
  BOTTOM w0.091: v1(64.3,71.1) 64.3,67.02 v1(65.3,66.02) ; v1(90.02,60.37) 90.18,60.21 90.18,58.89 88.22,56.92 88.22,55.48 v1(88.49,55.21)
TCPC1_NINT: length 132.7
  TOP w0.091: v1(56.19,56) 55.91,55.71 55.91,50.86 54.08,49.03 51.29,49.03 47.72,45.46 35.77,45.46 34.41,44.11 34.41,32.21 36,30.63 37.18,30.63 38.47,29.34 38.47,21.59 38.49,21.58 38.49,20.95 38.2,20.66 R431.2 37.85,20.19 38.12,19.92 U401.10 ; R823.1 103.16,55.84 101.03,57.96 101.03,59.9 95.98,64.95 95.98,65.1 91.45,69.64 70.4,69.64 70.23,69.81 61.07,69.81 57.83,73.05 v1(55.02,73.05)
  BOTTOM w0.091: v1(56.19,56) 55.73,56.46 55.73,70.83 55.02,71.55 v1(55.02,73.05)
TCPC_NINT: length 99.5
  TOP w0.091: v1(65.43,9.49) TP310.1 66.4,10.47 R1765.2 67.84,11.05 U301.10 ; v1(111.99,17.58) 112.86,18.46 112.86,22.61 114.26,24.01 114.26,36.9 114.1,37.07 v1(114.1,37.51) ; R805.2 v1(105.45,56.66)
  BOTTOM w0.091: v1(105.45,56.66) 106.76,55.34 106.76,53.1 112.68,47.19 112.68,37.92 113.09,37.51 v1(114.1,37.51) ; v1(65.43,9.49) 65.91,9.01 72.76,9.01 77.22,13.47 108.28,13.47 111.99,17.17 v1(111.99,17.58)
TEMP_SCL: length 1.4
  BOTTOM w0.091: U915.B2 115.83,77.26 R861.2
TEMP_SDA: length 1.3
  BOTTOM w0.091: R862.2 115.86,76.8 U915.C2
UART1_RXD: length 128.6
  TOP w0.081: 90.75,56.86 90.75,56.46 U101.B13
  TOP w0.091: v1(49.66,53.13) 48.96,52.42 48.96,51.34 46.72,49.1 43.79,49.1 43.08,48.39 32.69,48.39 31.65,49.43 31.65,55.01 30.99,55.66 27.08,55.66 24.58,53.16 24.58,51.23 22.37,49.02 17.74,49.02 14.78,51.98 14.78,53.43 14.54,53.66 12.98,53.66 TP612.1 12.2,52.88 R1720.2 ; v1(52.52,71.32) 52.61,71.41 57.93,71.41 60.62,68.72 69.47,68.72 69.78,68.41 91.13,68.41 94.18,65.36 94.18,61.95 90.75,58.51 90.75,56.86
  BOTTOM w0.091: v1(49.66,53.13) 50.81,54.28 50.81,69.41 52.52,71.11 v1(52.52,71.32)
UART1_TXD: length 133
  TOP w0.091: v1(51.42,71.45) 51.45,71.45 51.96,70.94 52.68,70.94 52.92,71.19 57.81,71.19 60.49,68.5 69.38,68.5 69.69,68.19 91.04,68.19 93.94,65.29 93.94,62.02 90.49,58.57 U101.A13 ; TP601.1 34.65,50.19 34.27,49.81 34.27,49.22 34.66,48.83 42.77,48.83 43.48,49.54 46.54,49.54 48.49,51.49 48.49,53.03 v1(48.59,53.13) ; TP601.1 32.53,52.63 32.53,54.85 31.28,56.1 26.9,56.1 24.14,53.34 24.14,51.41 22.19,49.46 17.92,49.46 15.22,52.16 15.22,53.61 14.73,54.1 9.52,54.1 TP610.1 8.91,52.6 R1723.2 ; TP601.1 34.69,50.55 R608.2
  BOTTOM w0.091: v1(48.59,53.13) 48.59,53.57 50.38,55.35 50.38,70.41 v1(51.42,71.45)
UART2_RXD: length 133.2
  TOP w0.081: U101.D14 91.74,55.95 91.74,56.34 91.85,56.46 92.14,56.46 92.25,56.57 92.25,57.43 92.7,57.89 v1(92.7,58)
  TOP w0.091: v1(94.23,61.3) 94.27,61.27 94.71,61.27 94.99,61.54 94.99,65.17 91.32,68.84 70.23,68.84 69.91,69.16 60.8,69.16 57.78,72.18 52.64,72.18 v1(51.95,71.49) ; v1(49.13,53.13) 48.73,52.73 48.73,51.42 46.63,49.32 43.57,49.32 42.86,48.61 32.78,48.61 32.31,49.08 32.31,54.65 31.08,55.88 26.99,55.88 24.36,53.25 24.36,51.32 22.28,49.24 17.83,49.24 15,52.07 15,53.52 14.64,53.88 11.81,53.88 TP616.1 11.07,52.96 R1721.2
  BOTTOM w0.081: 92.96,58.37 92.96,58.26 v1(92.7,58)
  BOTTOM w0.091: v1(94.23,61.3) 94.1,61.3 92.96,60.17 92.96,58.37 ; v1(49.13,53.13) 49.13,53.35 50.59,54.82 50.59,69.98 51.95,71.33 v1(51.95,71.49)
UART2_TXD: length 139.2
  TOP w0.081: v1(90.49,55.21) U101.D12
  TOP w0.091: TP602.1 34.65,51.36 v1(34.72,51.29) ; TP602.1 34.69,52.88 R607.2 ; TP602.1 32.75,54.74 32.75,55.06 31.49,56.32 26.81,56.32 23.92,53.43 23.92,51.5 22.1,49.68 18.01,49.68 15.44,52.25 15.44,53.7 14.82,54.32 8.55,54.32 TP614.1 7.8,52.52 R1724.2 ; v1(48.06,53.13) 48.06,51.37 46.45,49.76 43.39,49.76 42.68,49.05 34.97,49.05 v1(34.65,49.37) ; v1(52.01,72.08) 52.33,72.4 57.87,72.4 60.89,69.38 70.05,69.38 70.36,69.06 91.41,69.06 95.36,65.11 v1(95.36,61.72)
  BOTTOM w0.091: v1(52.01,72.08) 51.51,72.08 50.16,70.73 50.16,55.89 48.06,53.79 v1(48.06,53.13) ; v1(34.65,49.37) 34.65,51.22 v1(34.72,51.29) ; v1(95.36,61.72) 95.18,61.72 93.18,59.72 93.18,56.93 91.57,55.32 90.61,55.32 v1(90.49,55.21)
UART5_CTSI: length 82.6
  TOP w0.091: J1707.34 125.1,17.12 125.4,17.42 125.4,19.33 v1(125.19,19.53)
  TOP w0.102: v1(75.44,19.11) 76.02,19.69 76.02,23.74 77.67,25.39 77.67,33.83 78.33,34.49 78.33,36.5 81.48,39.65 81.48,41.31 R416.2
  BOTTOM w0.091: v1(125.19,19.53) 124.42,20.31 119.8,20.31 119.44,19.95 76.28,19.95 v1(75.44,19.11)
UART5_RTSO: length 4.4
  TOP w0.091: J1707.36 124.6,17.34 124.92,17.65 R419.2
UART5_RXD: length 4.2
  TOP w0.091: J1707.22 128.1,16.75 128.46,17.1 R417.2
UART5_TXD: length 83.7
  TOP w0.091: v1(125.78,19.57) 125.78,19.56 125.78,16.45 125.6,16.27 J1707.32
  TOP w0.102: R414.2 81.22,42.05 81.22,39.7 78.11,36.59 78.11,34.59 77.44,33.93 77.44,25.48 75.79,23.83 75.79,20.13 v1(74.78,19.11)
  BOTTOM w0.091: v1(74.78,19.11) 75.83,20.17 119.35,20.17 119.71,20.53 124.82,20.53 v1(125.78,19.57)
USB1_CC1: length 8.6
  TOP w0.091: U411.A2 33.09,18.77 32.63,19.22 32.63,20.36 33.63,21.36 34.42,21.36 34.7,21.08 34.7,20.08 35.9,18.88 U401.13
USB1_CC2: length 3.2
  TOP w0.091: U411.B2 U411.C2 U411.C1 34.34,18.18 34.49,18.03 U401.14
USB1_DN: length 126.9
  TOP w0.091: 29.59,11.64 TP611.1
  TOP w0.102: U403.C1 29.5,9.98 29.5,10.66 TP611.1 ; 29.59,11.64 29.59,12.12 29.69,12.22 v1(29.7,12.22) ; U101.A4 85.96,56.74 85.96,57.62 85.89,57.69 85.61,57.97 85.61,60.48 84.39,61.7 82.9,61.7 82.52,62.07 68.58,62.07 64.64,58.13 56.31,58.13 54.53,56.35 54.53,51.13 53.91,50.51 51.39,50.51 46.95,46.07 35.11,46.07 33.51,44.47 33.51,26.76 32.51,25.76 21.67,25.76 20.8,24.89 20.8,10.73 v1(20.61,10.54)
  BOTTOM w0.102: v1(29.7,12.22) 29.61,12.22 29.51,12.12 29.51,11.1 28.05,9.65 20.93,9.65 20.61,9.96 v1(20.61,10.54)
USB1_DP: length 126.9
  TOP w0.081: 85.74,56.8 85.74,56.46 U101.B4
  TOP w0.091: TP613.1 29.32,11.83
  TOP w0.102: v1(28.98,12.32) 29.18,12.32 29.32,12.18 29.32,11.83 ; v1(21.16,10.51) 21.02,10.65 21.02,24.8 21.76,25.55 32.6,25.55 33.72,26.67 33.72,44.38 35.2,45.85 47.04,45.85 51.48,50.29 54,50.29 54.74,51.04 54.74,56.26 56.4,57.92 64.73,57.92 68.67,61.86 82.43,61.86 82.81,61.48 84.3,61.48 85.39,60.39 85.39,57.88 85.74,57.53 85.74,56.8 ; U403.C2 29.27,9.98 29.27,10.51 TP613.1
  BOTTOM w0.102: v1(28.98,12.32) 29.19,12.32 29.29,12.22 29.29,11.19 27.97,9.86 21.02,9.86 20.84,10.04 20.84,10.22 21.12,10.51 v1(21.16,10.51)
USB1_ID: length 12.6
  TOP w0.081: U101.D4 v1(86.49,55.21)
  TOP w0.091: R1767.2 v1(80.51,63.2) 80.52,63.2 TP1924.1
  BOTTOM w0.091: v1(86.49,55.21) 86.13,55.57 86.13,57.57 82.61,61.09 82.61,61.64 82.32,61.94 81.57,61.94 80.51,63 v1(80.51,63.2)
USB1_VBUS_3V3: length 2.8
  TOP w0.305: R1768.2 24.75,29.96 R301.2 23.62,31.51 U404.1
USB_CC1_PD: length 35.5
  TOP w0.091: v1(43.03,9.51) TP301.1 42.91,8.62 J301.A5 ; R350.1 70.72,4.52 70.54,4.7 70.54,5.2 v1(70.62,5.28) 70.75,5.41 71.76,5.41 71.85,5.51 R358.1
  BOTTOM w0.091: v1(43.03,9.51) 43.81,8.73 47.05,8.73 50.5,5.28 v1(70.62,5.28)
USB_CC1_PD_OVP: length 7.6
  TOP w0.254: U303.A1 72.41,4.82 72.11,4.52 R350.2 R356.2
USB_CC2_PD: length 25.7
  TOP w0.091: v1(44.3,9.45) 44.3,8.34 TP303.1 43.91,7.95 J301.B5 ; v1(63.24,8.2) 63.3,8.14 R351.1
  TOP w0.254: R359.1 63.96,7.6 63.97,7.6 R351.1
  BOTTOM w0.091: v1(63.24,8.2) 61.87,6.83 49.26,6.83 46.64,9.45 v1(44.3,9.45)
USB_CC2_PD_OVP: length 19.5
  TOP w0.203: v1(72.94,8.6) 72.85,8.7 72.85,11.15 72.64,11.36 U303.B1
  TOP w0.254: R351.2 67.38,8.14 v1(67.79,7.74) 67.79,5.39 67.43,5.03 64.65,5.03 63.81,4.19 R357.2
  BOTTOM w0.203: v1(72.94,8.6) 68.66,8.6 v1(67.79,7.74)
USB_DBG_CC1: length 2.2
  TOP w0.091: R1488.1 14.56,8.36 J1708.A5
USB_DBG_CC2: length 11.6
  TOP w0.091: R1489.1 v1(17.91,9.05)
  BOTTOM w0.091: J1708.B5 16.11,4.88 16.7,4.29 19.15,4.29 20.38,5.51 20.38,5.55 20.68,5.85 20.68,7.71 19.34,9.05 v1(17.91,9.05)
USB_DBG_DN: length 4.3
  TOP w0.102: J1708.A7 15.56,7.77 v1(15.58,7.78) 15.42,7.95 15.42,9.01 U1403.A1
  BOTTOM w0.102: J1708.B7 14.91,7.12 v1(15.58,7.78)
USB_DBG_DP: length 3.5
  TOP w0.102: J1708.B6 15.06,6.59 J1708.A6 15.06,7.77 15.2,7.91 15.2,9 U1403.A2
USB_I2C_SCL: length 91
  TOP w0.091: U301.8 65.27,12.84 R1008.2 R1015.2 R1017.2 64.72,9.54 v1(64.79,9.47) ; v1(42.41,18.19) R1777.2 41.83,19.32 R420.2
  BOTTOM w0.091: v1(64.79,9.47) 64.67,9.6 51.01,9.6 v1(42.41,18.19) 40.38,20.23 37.15,20.23 36.25,19.34 35.67,19.34 34.4,20.61 33.58,20.61 33.38,20.81 33.38,21.81 35.65,24.07 47.04,24.07 48.09,25.12 48.09,27.28 45.74,29.63 45.74,38.44 45.01,39.17 45.01,44.2 46.39,45.59 46.39,47.37 47.27,48.25 47.27,51.72 47.07,51.92 R1073.1
USB_I2C_SDA: length 94.1
  TOP w0.091: v1(61.73,14.06) 61.93,13.86 61.93,10.57 v1(63.36,9.14) ; R1778.2 R421.2 v1(42.36,15.84) ; U301.7 64.93,13.24 R1018.2 R1016.2 ; v1(65.35,14.01) 64.97,14.38 R1016.2 ; R1016.2 R1009.2
  BOTTOM w0.091: v1(63.36,9.14) 50.85,9.14 44.15,15.84 v1(42.36,15.84) 38.24,19.97 37.2,19.97 36.34,19.12 35.58,19.12 34.31,20.38 33.46,20.38 33.17,20.68 33.17,21.9 35.56,24.29 46.95,24.29 47.87,25.21 47.87,27.19 45.52,29.54 45.52,38.35 44.79,39.08 44.79,44.29 46.17,45.68 46.17,48.41 R1074.1 ; v1(61.73,14.06) 61.78,14.01 v1(65.35,14.01)
USB_PD_VBUS: length 7
  TOP w0.508: J301.A9 v1(44.93,7.54) ; J301.B9 v1(41.89,7.69) 41.89,8.1 41.6,8.39 F301.1
  BOTTOM w0.508: v1(41.89,7.69) 44.78,7.69 v1(44.93,7.54)
USB_PD_VBUS_F: length 50.1
  TOP w0.254: R305.1 v1(50.45,22.72) R304.1 51.19,24.25 51.19,25.38 50.23,26.34 48.56,26.34 ; U301.15 v1(70.36,13.24)
  TOP w0.508: v1(32.77,30.1) 31.94,29.26 D401.A
  BOTTOM w0.254: v1(50.45,22.72) 50.45,21.07 58.29,13.24 66.07,13.24 66.81,13.98 69.62,13.98 v1(70.36,13.24)
  BOTTOM w0.508: v1(32.77,30.1) 42.75,30.1 v1(46.84,26.01)
  vias: v1(37.6,12.5) v1(37.68,11.99) v1(38.15,12.58) v1(38.19,12.08) v1(46.81,25.22) v1(47.31,25.19) v1(47.42,25.97)
USBC_CC1: length 15.3
  TOP w0.091: v1(33.44,16.54) 33.44,16.89 33.54,16.98 U411.A1 ; v1(28.56,9.02) 28.55,9.02 TP1928.1 28.68,8.21 J1101.A5
  BOTTOM w0.091: v1(28.56,9.02) 30.11,9.02 33.21,12.11 33.21,16.31 v1(33.44,16.54)
USBC_CC2: length 18.5
  TOP w0.091: v1(34.68,16.51) 34.53,16.65 TP1929.1 33.94,16.73 U411.B1
  BOTTOM w0.091: J1101.B5 30.99,4.48 33.47,4.48 34.68,5.69 v1(34.68,16.51)
USBC_DN: length 3.5
  TOP w0.102: U403.A1 29.53,9.05 29.53,7.97 29.68,7.82 29.68,7.06 J1101.A7 29.68,6.59 J1101.B7
USBC_DP: length 4.3
  TOP w0.102: J1101.A6 29.18,7.81 v1(29.19,7.81) 29.19,7.91 29.28,8 29.28,9.01 U403.A2
  BOTTOM w0.102: v1(29.19,7.81) 29.19,6.58 J1101.B6
USBC_EN_SNK1: length 8.6
  TOP w0.091: U401.2 37.32,15.87 36.94,15.49 33.61,15.49 32.16,16.94 32.16,17.81 31.74,18.23 R411.1
USBC_EN_SRC1: length 8
  TOP w0.091: R410.1 31.47,19.34 32.53,18.28 32.53,16.88 33.28,16.13 34.86,16.13 35.96,17.23 U401.16
USBC_I2C_SCL: length 2.2
  TOP w0.091: U401.8 40.91,18.03 R1777.1
USBC_I2C_SDA: length 2.4
  TOP w0.091: U401.7 40.41,17.63 R1778.1
USBC_SBU1: length 2.9
  TOP w0.091: J1101.A8 30.18,8.31 30.74,8.87 TP1930.1
USBC_SBU2: length 8.3
  TOP w0.091: TP1931.1 22.46,6.23 24.26,4.43 27.82,4.43 J1101.B8
USBC_VBUS: length 11.1
  TOP w0.254: F401.1 26.49,10.22 TP609.1 ; 28.19,7.1 28.19,6.04 28.24,5.99
  TOP w0.381: J1101.A9 30.68,5.99 J1101.B4
  BOTTOM w0.381: J1101.B9 28.23,8.02 28.54,8.34 30.06,8.34 30.63,7.77 J1101.B4
USBC_VBUS_F: length 32.9
  TOP w0.254: U401.15 v1(35.59,17.63)
  TOP w0.305: 27.32,28.19 27.97,28.19 28.13,28.03 28.13,26.58 28.58,26.13 31.13,26.13 D402.A
  TOP w0.381: R360.1 27.81,29.23 R1769.1 26.94,28.33 R1770.1
  TOP w0.508: 27.32,28.19 R1770.1 26.05,28.19 v1(25.75,27.89)
  BOTTOM w0.254: v1(26.08,18.55) 26.08,16.58 27.66,15 30.95,15 33.57,17.63 v1(35.59,17.63)
  BOTTOM w0.508: v1(25.75,27.89) 26.01,27.63 26.01,19.7 v1(26.04,19.66)
  vias: v1(22.33,11.63) v1(22.33,11.07) v1(22.97,11.62) v1(22.98,11.05) v1(23.59,11.63) v1(23.63,11.07) v1(25.45,19.69) v1(26.67,19.6)
VBBS: length 2.5
  BOTTOM w0.203: U1004.14 38.39,51.54 C1021.1
VEN_SPI_CLK/UART_RTSO: length 12.3
  TOP w0.091: R944.1 123.17,25.62 123.17,15.42 123.1,15.35 J1707.42
VEN_SPI_FRM/UART_CTSI: length 21.2
  TOP w0.091: R957.2 114.6,18.62 v1(114.55,18.62) ; v1(124.12,25.02) 124.46,24.69 124.46,23.94 124.14,23.62 124.14,18.82 v1(124.22,18.75)
  BOTTOM w0.091: v1(114.55,18.62) 115,19.08 119.81,19.08 119.85,19.12 123.84,19.12 v1(124.22,18.75) ; R945.1 121.76,25.94 R941.1 122.36,25.34 123.81,25.34 v1(124.12,25.02)
VEN_SPI_RXD/UART_SIN: length 12.3
  TOP w0.091: J1707.40 123.6,25.52 R943.1
VEN_SPI_TXD/UART_SOUT: length 15.3
  TOP w0.091: v1(121.79,25.12) R942.1 121.78,25.93 R938.1 ; J1707.38 124.1,15.4 123.84,15.66 123.84,24.18 v1(124.04,24.38)
  BOTTOM w0.091: v1(124.04,24.38) 124.04,24.44 123.36,25.12 v1(121.79,25.12)
VLDO1_3V3: length 2
  TOP w0.203: U402.A5 25.91,15.52 25.24,14.85 C410.1
VLDO3_1V8: length 27.5
  TOP w0.254: 62.69,35.33 63.31,34.7 U701.54
  TOP w0.381: v1(56.92,32.24) 56.92,37.63 58.76,39.47 60.05,39.47 60.88,38.64 TP711.1 60.66,37.85 60.66,36.37 61.3,35.73 C729.1 62.29,35.73 62.69,35.33
  BOTTOM w0.381: R111.1 60.05,23.49 56.92,26.62 v1(56.92,32.24)
VLDO_3V3: length 125
  TOP w0.203: v1(33.13,19.5) 33.46,19.17 U411.A3
  TOP w0.254: v1(70.67,10.42) 71.12,9.98 C305.1 71.61,10.35 U303.A3 ; U402.A1 27.55,15.75 27.83,15.47 v1(27.84,15.47) ; v1(48.58,20.38) 50.2,20.38 50.46,20.63 R1758.1 50.67,20.93 51.25,20.35 53.08,20.35 R1763.1
  TOP w0.381: v1(31.21,34.39) 30.97,34.64 30.97,35.9 30.13,36.74 U405.1 29.72,36.84 C412.1 ; v1(33.8,20.98) 33.8,20.92 33.13,20.25 v1(33.13,19.5)
  BOTTOM w0.254: v1(48.58,20.38) 56.83,12.13 69.76,12.13 70.67,11.21 v1(70.67,10.42)
  BOTTOM w0.381: 48.58,22.62 v1(48.58,20.38) ; 48.58,22.62 47.86,23.34 35.68,23.34 33.8,21.46 v1(33.8,20.98) ; 48.58,22.62 49.68,23.72 49.68,26.76 48.88,27.56 48.88,45.26 47.63,46.51 47.63,52.29 47.52,52.4 47.52,53.18 47.03,53.67 46.59,53.67 R1077.1 46.22,55.06 45.84,55.44 D1012.A 44.71,56.34 45.09,56.72 46.62,56.72 47.14,57.24 D1011.A ; v1(27.84,15.47) 28.01,15.65 C408.1 29.39,15.65 32.08,18.34 33.01,18.34 C418.1 33.31,19.5 v1(33.13,19.5) 32.8,19.83 32.8,27.52 31.52,28.81 31.52,34.09 v1(31.21,34.39)
VMIC_1V8: length 273.7
  TOP w0.254: C1308.1 76.63,5.92 75.58,6.97 U1302.4 ; C1304.1 6.27,5.47 4.74,7 U1301.4 U1301.3 4.74,8.87 5.34,9.47 C1301.1 ; C1310.1 6.73,73.39 6.42,73.7 6.42,76.12 4.74,77.8 U1304.4 ; U1305.4 75.58,77.85 76.17,77.26 76.17,76.4 C1317.1 74.68,74.91 C1318.1 74.68,73.84 74.42,73.59 73.15,73.59 70.55,76.19 70.55,82.56 69.05,84.07 23.23,84.07 22.29,83.14 16.51,83.14 v1(16.39,83.02) 16.25,82.87 7.38,82.87 6.76,82.25 6.49,82.25 C1309.1 6.09,81.04 4.74,79.69 U1304.3
  TOP w0.381: C1307.1 75.76,2.42 75.91,2.28 v1(76.02,2.28) C1308.1 ; 15.8,76.92 16.04,77.15 16.04,77.67 16.26,77.9 v1(16.26,79.78) ; C1304.1 v1(7.04,4.75) ; U1309.5 18.29,80.92 C1462.1 16.43,80.88 v1(16.26,81.06) ; C1310.1 v1(7.68,72.61) 7.78,72.61 8.39,72 9.07,72 9.24,72.17 R1814.2 10.08,71.83 10.32,71.58 14.48,71.58 14.86,71.96 C1302.1 ; U1304.4 U1304.3
  BOTTOM w0.254: v1(7.68,72.61) 7.68,70.47 3.16,65.95 3.16,26.57 5.84,23.89 5.84,15.49 3.16,12.81 3.16,8.62 v1(7.04,4.75) 8.6,3.18 52.25,3.18 53.59,4.53 63.11,4.53 64.59,3.05 75.25,3.05 v1(76.02,2.28)
  BOTTOM w0.381: v1(16.39,83.02) 16.26,82.88 v1(16.26,81.06) v1(16.26,79.78)
VPCIE_3V3: length 127
  TOP w0.381: L1403.1 82.66,75.28 82.07,75.87 v1(82.07,79.46) ; v1(116.24,21.38) 116.17,21.31 R936.1 ; R1790.2 v1(132.59,20.83) ; v1(130.52,19.8) 130.62,19.91 R1791.2
  TOP w0.457: R918.1 v1(121.71,18.14) 121.86,18.29 121.86,21.71 v1(121.78,21.78) ; 132.33,36.24 132.33,36.7 131.89,37.13 C1749.1 130.55,37.13 130.53,37.12 R902.1 130.11,37.95 129.78,38.27 128.78,38.27 127.79,37.29 127.79,35.68 C1753.2 ; R924.1 v1(129.56,19.11)
  TOP w0.508: v1(131.86,49.56) 133.02,50.72 133.02,60.38 129.94,63.47 v1(128.09,63.47)
  BOTTOM w0.381: 119.9,13 119.87,12.97 R917.1
  BOTTOM w0.457: v1(121.78,21.78) 121.68,21.68 119.21,21.68 118.9,21.38 v1(116.24,21.38)
  BOTTOM w0.508: v1(128.09,63.47) 128.09,77.43 123.16,82.36 83.45,82.36 82.07,80.98 v1(82.07,79.46) ; v1(131.86,49.56) 131.02,48.72 131.02,37.11 v1(132.49,35.65)
  vias: v1(110.75,10.8) v1(111.45,10.75) v1(112.22,10.73) v1(133.28,35.61) v1(135.34,14.24) v1(135.33,13.63) v1(135.34,12.98) v1(135.51,36.44)
